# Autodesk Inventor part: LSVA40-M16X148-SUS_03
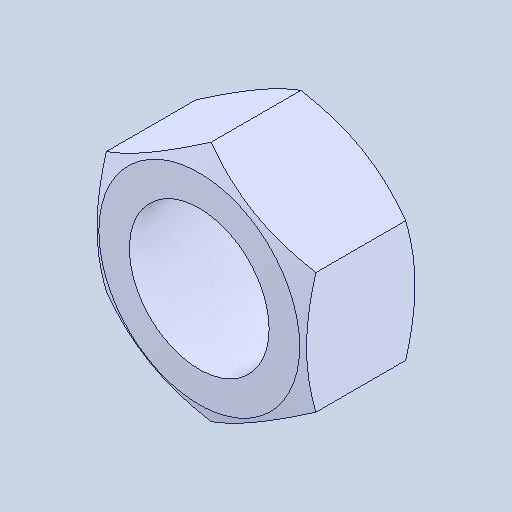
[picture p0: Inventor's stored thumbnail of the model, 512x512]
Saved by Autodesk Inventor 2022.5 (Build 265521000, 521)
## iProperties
Created: 2024-08
Part Number: LSVA40-M16X148-SUS_03
Material: 一般
Document SubType Name: Modeling
Designer: ImaoCorp
Density: 1 g/cm^3
Appearance: 既定
Author: ImaoCorp
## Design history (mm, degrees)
feature "LSVA40-M16X148-SUS_03"
node "ソリッド1"
